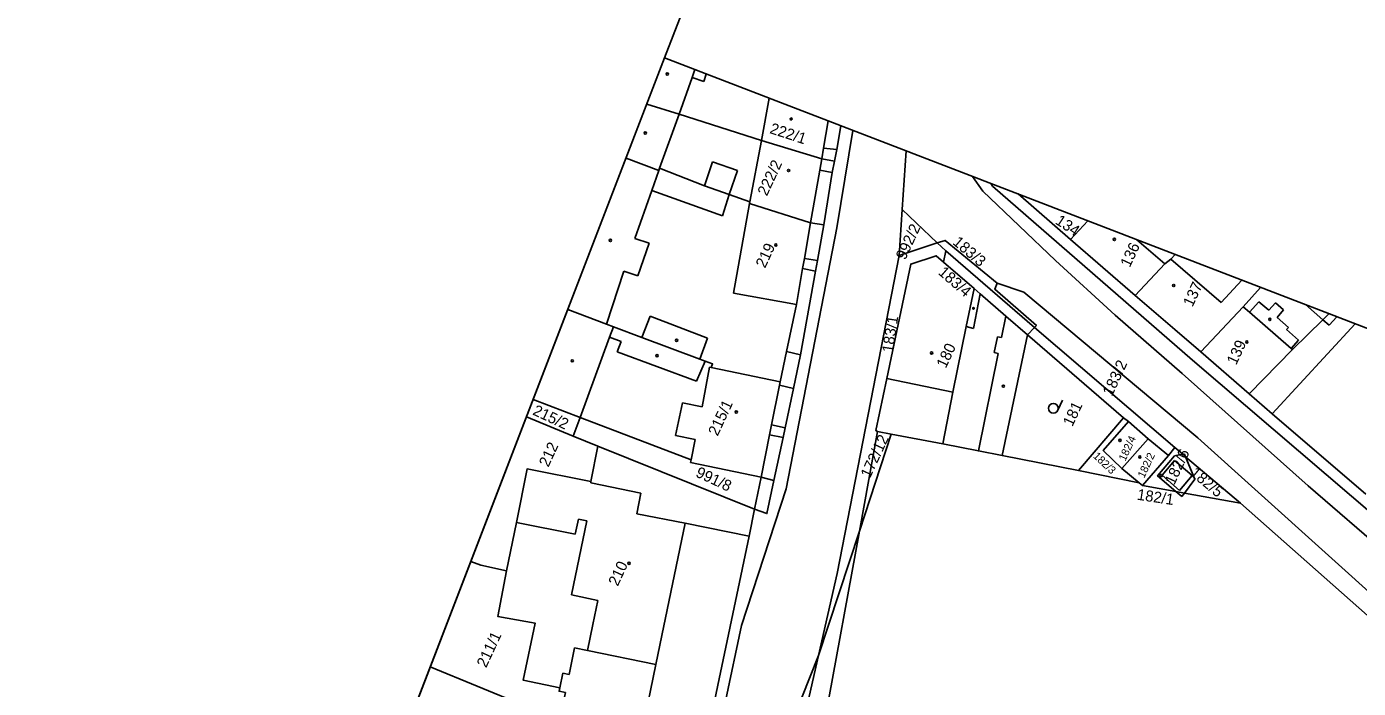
# Model space of a CAD drawing. Extents: x -755344 to -754412, y -1162670 to -1161477.
# Drawn here: x -755140.6 to -754935.5, y -1161770.1 to -1161668.2 of the extents above; entities that cross this region are included whole.
import ezdxf

# ---------------------------------------------------------------- set-up
doc = ezdxf.new("R2010")
doc.units = 0
for name, color, linetype in [('Formát', 7, 'Continuous'), ('Vrstva 55', 7, 'Continuous'), ('Vrstva 56', 7, 'Continuous'), ('Vrstva 57', 7, 'Continuous'), ('Vrstva 58', 7, 'Continuous'), ('Vrstva 59', 7, 'Continuous')]:
    doc.layers.add(name, color=color, linetype=linetype)

msp = doc.modelspace()

# ---------------------------------------------------------------- linework, layer by layer
at = {"layer": 'Formát'}
for q in [(-754966.95, -1161477.04), (-755344.08, -1162456.97), (-755344.08, -1162456.97)]:
    msp.add_line((-755042.37, -1161673.02), q, dxfattribs=at)
msp.add_lwpolyline([(-754488.01, -1161886.37), (-754789.71, -1162670.32), (-755344.08, -1162456.97), (-755042.37, -1161673.02)], close=True, dxfattribs=at)
for points in [[(-755344.08, -1162456.97), (-754789.71, -1162670.32), (-754488.01, -1161886.37), (-755042.37, -1161673.02)], [(-755344.08, -1162456.97), (-754789.71, -1162670.32), (-754488.01, -1161886.37), (-755042.37, -1161673.02)], [(-754789.71, -1162670.32), (-754488.01, -1161886.37), (-755042.37, -1161673.02), (-755344.08, -1162456.97)]]:
    msp.add_lwpolyline(points, dxfattribs=at)
at = {"layer": 'Vrstva 55'}
for p, q in [((-754987.94, -1161693.97), (-754979.83, -1161700.97)), ((-755005.78, -1161696.36), (-755006.24, -1161703.45)), ((-755000.37, -1161701.51), (-755005.78, -1161696.36)), ((-755006.24, -1161703.45), (-755000.37, -1161701.51)), ((-754999.07, -1161702.74), (-755000.37, -1161701.51)), ((-754979.83, -1161700.97), (-754969.9, -1161709.58)), ((-754999.42, -1161704.46), (-754999.07, -1161702.74)), ((-754999.07, -1161702.74), (-754985.41, -1161714.55)), ((-754948.77, -1161727.83), (-754936.01, -1161713.96)), ((-754990.38, -1161734.22), (-754986.49, -1161715.65)), ((-754985.41, -1161714.55), (-754986.49, -1161715.65)), ((-754971.69, -1161728.46), (-754986.49, -1161715.65)), ((-754963.8, -1161733.02), (-754985.41, -1161714.55)), ((-754959.79, -1161718.27), (-754952.34, -1161724.76)), ((-754952.34, -1161724.76), (-754948.77, -1161727.83)), ((-754978.64, -1161736.57), (-754971.69, -1161728.46)), ((-754970.94, -1161729.03), (-754971.69, -1161728.46)), ((-754948.77, -1161727.83), (-754934.36, -1161740.2)), ((-755009.58, -1161730.57), (-755012.38, -1161745.91)), ((-755009.58, -1161730.57), (-755007.48, -1161730.96)), ((-754967.88, -1161731.67), (-754970.94, -1161729.03)), ((-755012.38, -1161745.91), (-755007.48, -1161730.96)), ((-754967.88, -1161731.67), (-754971.93, -1161736.25)), ((-754964.78, -1161734.24), (-754967.88, -1161731.67)), ((-755028.51, -1161742.5), (-755052.64, -1161732.78)), ((-754990.38, -1161734.22), (-754978.64, -1161736.57)), ((-754964.78, -1161734.24), (-754968.79, -1161738.86)), ((-754963.8, -1161733.02), (-754964.78, -1161734.24)), ((-754962.57, -1161734.06), (-754963.8, -1161733.02)), ((-754962.13, -1161734.44), (-754962.57, -1161734.06)), ((-754953.69, -1161741.58), (-754962.13, -1161734.44)), ((-754978.64, -1161736.57), (-754969.27, -1161738.43)), ((-754971.93, -1161736.25), (-754969.27, -1161738.43)), ((-755028.51, -1161742.5), (-755027.52, -1161737.6)), ((-755027.52, -1161737.6), (-755025.54, -1161738.11)), ((-754969.27, -1161738.43), (-754968.79, -1161738.86)), ((-754968.79, -1161738.86), (-754963.61, -1161739.79)), ((-754963.61, -1161739.79), (-754962.32, -1161740.03)), ((-754962.32, -1161740.03), (-754953.69, -1161741.58)), ((-755029.37, -1161746.66), (-755028.51, -1161742.5)), ((-755036.5, -1161780.73), (-755029.37, -1161746.66)), ((-755018.69, -1161780.44), (-755012.38, -1161745.91)), ((-755012.38, -1161745.91), (-755018.66, -1161765.05)), ((-755018.66, -1161765.05), (-755023.99, -1161778.44)), ((-755063.99, -1161772.75), (-755078.47, -1161766.81))]:
    msp.add_line(p, q, dxfattribs=at)
for points in [[(-755045.1, -1161680.12), (-755040.15, -1161681.69), (-755027.46, -1161685.72), (-755018.17, -1161688.54), (-755016.23, -1161688.9)], [(-755013.38, -1161684.18), (-755015.84, -1161699.17), (-755023.66, -1161739.37), (-755030.54, -1161760.43), (-755032.94, -1161771.83), (-755032.59, -1161783.86), (-755042.91, -1161835.1), (-755052.57, -1161882.7), (-755054.53, -1161882.87), (-755056.71, -1161887.12)], [(-755016.23, -1161688.9), (-755015.87, -1161687.12), (-755015.22, -1161683.47)], [(-755005.78, -1161696.36), (-755005.19, -1161687.33)], [(-755017.87, -1161698.7), (-755019.88, -1161698.39), (-755029.28, -1161695.42), (-755029.22, -1161695.16), (-755032.44, -1161694.05), (-755036.25, -1161692.73), (-755043.15, -1161689.97), (-755043.28, -1161690.35), (-755048.31, -1161688.46)], [(-755017.87, -1161698.7), (-755016.58, -1161690.66), (-755016.23, -1161688.9)], [(-754992.13, -1161692.36), (-754991.87, -1161692.75), (-754961.05, -1161719.56), (-754924.16, -1161751.14), (-754883.24, -1161788.9), (-754859.67, -1161809.81)], [(-755022.5, -1161723.9), (-755021.42, -1161718.75), (-755019.14, -1161705.86), (-755018.84, -1161704.19), (-755017.87, -1161698.7)], [(-754979.83, -1161700.97), (-754977.18, -1161698.11)], [(-754985.41, -1161714.55), (-754985.11, -1161714.24), (-754991.52, -1161708.65), (-754991.16, -1161707.68), (-754999.16, -1161701.11), (-755000.37, -1161701.51)], [(-755006.24, -1161703.45), (-755015.79, -1161752.42), (-755018.66, -1161765.05)], [(-754999.42, -1161704.46), (-755000.57, -1161703.47), (-755004.47, -1161704.76), (-755008.12, -1161722.39), (-755009.83, -1161730.4), (-755009.58, -1161730.57)], [(-754969.9, -1161709.58), (-754965.35, -1161704.72), (-754964.42, -1161704), (-754963.75, -1161703.28)], [(-754986.49, -1161715.65), (-754989.82, -1161712.77), (-754993.77, -1161709.36), (-754994.71, -1161708.54), (-754999.42, -1161704.46)], [(-754969.9, -1161709.58), (-754963.77, -1161714.86), (-754959.79, -1161718.27)], [(-754959.79, -1161718.27), (-754953.28, -1161711.36), (-754950.58, -1161708.35)], [(-755022.5, -1161723.9), (-755024.69, -1161723.43), (-755024.58, -1161722.88), (-755035.2, -1161720.68), (-755034.98, -1161720.14), (-755036.15, -1161719.7), (-755036.96, -1161719.39), (-755045.89, -1161716.05), (-755050.24, -1161714.41), (-755051.31, -1161714.01), (-755057.28, -1161711.76)], [(-754952.34, -1161724.76), (-754945.68, -1161717.94), (-754941, -1161713.33), (-754940.05, -1161712.4)], [(-755025.54, -1161738.11), (-755024.12, -1161731.47), (-755023.8, -1161729.98), (-755022.5, -1161723.9)], [(-755062.62, -1161725.64), (-755055.4, -1161728.39), (-755038.3, -1161734.91)], [(-755052.64, -1161732.78), (-755056.45, -1161731.25), (-755063.65, -1161728.31)], [(-754971.93, -1161736.25), (-754974.81, -1161733.49), (-754970.94, -1161729.03)], [(-755007.48, -1161730.96), (-754999.54, -1161732.44), (-754994.03, -1161733.53), (-754990.38, -1161734.22)], [(-755052.64, -1161732.78), (-755053.71, -1161738.24), (-755063.56, -1161736.32), (-755065.16, -1161744.58), (-755066.7, -1161752.01)], [(-754963.61, -1161739.79), (-754966.45, -1161737.38), (-754963.82, -1161734.29), (-754962.57, -1161734.06)], [(-754962.13, -1161734.44), (-754960.7, -1161737.88), (-754962.32, -1161740.03)], [(-755038.3, -1161734.91), (-755038.38, -1161735.3), (-755027.52, -1161737.6)], [(-755025.54, -1161738.11), (-755026.62, -1161743.19), (-755028.51, -1161742.5)], [(-754790.69, -1161920.17), (-754823.33, -1161865.1), (-754831.37, -1161854.01), (-754842.43, -1161841.79), (-754855.01, -1161828.87), (-754953.69, -1161741.58)], [(-755066.7, -1161752.01), (-755068.08, -1161759.03), (-755062.31, -1161760.06), (-755064.15, -1161768.86), (-755058.51, -1161770.01), (-755058.63, -1161770.54), (-755057.66, -1161770.75), (-755058.23, -1161773.52), (-755045.73, -1161776.2), (-755043.71, -1161766.41), (-755042.79, -1161761.96), (-755039.2, -1161744.67), (-755029.37, -1161746.66)], [(-755072.22, -1161750.59), (-755070.67, -1161751.12), (-755066.7, -1161752.01)]]:
    msp.add_lwpolyline(points, dxfattribs=at)
at = {"layer": 'Vrstva 56'}
for p, q in [((-755038.11, -1161676.04), (-755037.71, -1161674.82)), ((-755040.15, -1161681.69), (-755038.11, -1161676.04)), ((-755038.11, -1161676.04), (-755036.35, -1161676.66)), ((-755036.35, -1161676.66), (-755035.95, -1161675.52)), ((-755035.95, -1161675.52), (-755035.73, -1161675.58)), ((-755027.46, -1161685.72), (-755026.28, -1161679.22)), ((-755043.15, -1161689.97), (-755040.15, -1161681.69)), ((-755017.16, -1161682.73), (-755017.89, -1161686.93)), ((-755029.22, -1161695.16), (-755027.46, -1161685.72)), ((-755017.89, -1161686.93), (-755018.17, -1161688.54)), ((-755017.89, -1161686.93), (-755015.87, -1161687.12)), ((-755036.25, -1161692.73), (-755035.01, -1161689.04)), ((-755035.01, -1161689.04), (-755031.17, -1161690.35)), ((-755018.17, -1161688.54), (-755018.47, -1161690.29)), ((-755043.28, -1161690.35), (-755044.33, -1161693.43)), ((-755031.17, -1161690.35), (-755032.44, -1161694.05)), ((-755018.47, -1161690.29), (-755019.88, -1161698.39)), ((-755018.47, -1161690.29), (-755016.58, -1161690.66)), ((-754993.37, -1161693.51), (-754994.94, -1161691.28)), ((-755044.33, -1161693.43), (-755046.94, -1161700.81)), ((-755033.47, -1161697.33), (-755044.33, -1161693.43)), ((-754982.15, -1161704.19), (-754993.37, -1161693.51)), ((-755032.44, -1161694.05), (-755033.47, -1161697.33)), ((-755031.76, -1161709.25), (-755029.28, -1161695.42)), ((-755019.88, -1161698.39), (-755020.83, -1161703.89)), ((-755046.94, -1161700.81), (-755044.77, -1161701.56)), ((-755044.77, -1161701.56), (-755046.5, -1161706.59)), ((-754969.66, -1161701.01), (-754965.35, -1161704.72)), ((-755020.83, -1161703.89), (-755021.11, -1161705.47)), ((-755020.83, -1161703.89), (-755018.84, -1161704.19)), ((-755048.66, -1161705.85), (-755051.31, -1161714.01)), ((-755046.5, -1161706.59), (-755048.66, -1161705.85)), ((-755021.11, -1161705.47), (-755022.06, -1161710.98)), ((-755021.11, -1161705.47), (-755019.14, -1161705.86)), ((-754972.97, -1161712.61), (-754982.15, -1161704.19)), ((-754964.42, -1161704), (-754956.65, -1161710.67)), ((-754991.16, -1161707.68), (-754987.03, -1161709.11)), ((-754953.45, -1161707.25), (-754956.65, -1161710.67)), ((-755022.06, -1161710.98), (-755031.76, -1161709.25)), ((-754994.71, -1161708.54), (-754995.92, -1161714.4)), ((-754994.8, -1161714.66), (-754993.77, -1161709.36)), ((-754987.03, -1161709.11), (-754960.25, -1161731.5)), ((-755022.06, -1161710.98), (-755023.6, -1161718.23)), ((-754953.28, -1161711.36), (-754952.29, -1161712.19)), ((-754952.29, -1161712.19), (-754950.83, -1161710.56)), ((-754950.83, -1161710.56), (-754949.33, -1161711.87)), ((-754949.33, -1161711.87), (-754948.26, -1161710.72)), ((-754948.26, -1161710.72), (-754947.03, -1161711.83)), ((-754947.03, -1161711.83), (-754948.04, -1161712.99)), ((-754943.67, -1161711.01), (-754941, -1161713.33)), ((-755045.89, -1161716.05), (-755044.58, -1161712.76)), ((-755044.58, -1161712.76), (-755035.76, -1161716.18)), ((-754989.82, -1161712.77), (-754990.49, -1161716.08)), ((-754962.66, -1161721.63), (-754972.97, -1161712.61)), ((-754952.29, -1161712.19), (-754945.87, -1161717.78)), ((-754948.04, -1161712.99), (-754946.27, -1161714.52)), ((-754941, -1161713.33), (-754940.01, -1161714.16)), ((-754940.01, -1161714.16), (-754938.83, -1161712.87)), ((-755050.84, -1161716.03), (-755055.4, -1161728.39)), ((-755050.84, -1161716.03), (-755050.24, -1161714.41)), ((-755049.08, -1161716.71), (-755050.84, -1161716.03)), ((-755035.76, -1161716.18), (-755036.96, -1161719.39)), ((-754998, -1161724.47), (-754995.92, -1161714.4)), ((-754995.92, -1161714.4), (-754994.8, -1161714.66)), ((-754991.11, -1161715.96), (-754991.62, -1161718.4)), ((-754990.49, -1161716.08), (-754991.11, -1161715.96)), ((-754946.27, -1161714.52), (-754946.57, -1161714.86)), ((-754946.57, -1161714.86), (-754944.75, -1161716.46)), ((-755049.66, -1161718.28), (-755049.08, -1161716.71)), ((-755024.58, -1161722.88), (-755023.6, -1161718.23)), ((-755021.42, -1161718.75), (-755023.6, -1161718.23)), ((-754944.75, -1161716.46), (-754945.87, -1161717.78)), ((-754945.87, -1161717.78), (-754945.68, -1161717.94)), ((-755037.48, -1161722.82), (-755049.66, -1161718.28)), ((-755036.15, -1161719.7), (-755037.48, -1161722.82)), ((-754990.99, -1161718.52), (-754994.03, -1161733.53)), ((-754991.62, -1161718.4), (-754990.99, -1161718.52)), ((-755036.61, -1161726.74), (-755035.47, -1161720.63)), ((-755035.47, -1161720.63), (-755035.2, -1161720.68)), ((-754962.66, -1161721.63), (-754943.25, -1161738.89)), ((-755025.91, -1161729.53), (-755024.69, -1161723.43)), ((-755008.12, -1161722.39), (-754998, -1161724.47)), ((-755040.69, -1161731.15), (-755039.61, -1161726.11)), ((-755039.61, -1161726.11), (-755036.61, -1161726.74)), ((-754998, -1161724.47), (-754999.54, -1161732.44)), ((-755055.4, -1161728.39), (-755056.45, -1161731.25)), ((-755026.21, -1161731.04), (-755025.91, -1161729.53)), ((-755025.91, -1161729.53), (-755023.8, -1161729.98)), ((-755037.65, -1161731.78), (-755040.69, -1161731.15)), ((-755038.3, -1161734.91), (-755037.65, -1161731.78)), ((-755026.21, -1161731.04), (-755027.52, -1161737.6)), ((-755024.12, -1161731.47), (-755026.21, -1161731.04)), ((-754931.36, -1161757.54), (-754960.25, -1161731.5)), ((-754962.57, -1161734.06), (-754962.3, -1161734.02)), ((-754962.3, -1161734.02), (-754962.13, -1161734.44)), ((-754965.75, -1161737.28), (-754963.83, -1161735.02)), ((-754963.83, -1161735.02), (-754961.12, -1161737.33)), ((-755053.75, -1161738.45), (-755053.71, -1161738.24)), ((-755053.75, -1161738.45), (-755046.02, -1161740.06)), ((-754963.05, -1161739.61), (-754965.75, -1161737.28)), ((-754961.12, -1161737.33), (-754963.05, -1161739.61)), ((-755046.02, -1161740.06), (-755046.67, -1161743.21)), ((-754962.71, -1161740.56), (-754963.61, -1161739.79)), ((-754962.32, -1161740.03), (-754962.71, -1161740.56)), ((-754943.25, -1161738.89), (-754926.26, -1161753.63)), ((-755065.16, -1161744.58), (-755056.13, -1161746.34)), ((-755056.71, -1161755.68), (-755054.35, -1161744.29)), ((-755056.13, -1161746.34), (-755055.66, -1161744.06)), ((-755055.66, -1161744.06), (-755054.87, -1161744.19)), ((-755054.35, -1161744.29), (-755054.87, -1161744.19)), ((-755046.67, -1161743.21), (-755039.2, -1161744.67)), ((-755052.67, -1161756.55), (-755056.71, -1161755.68)), ((-755053.42, -1161760.28), (-755052.67, -1161756.55)), ((-755054.23, -1161764.27), (-755053.42, -1161760.28)), ((-755056.23, -1161763.86), (-755057.08, -1161767.98)), ((-755054.23, -1161764.27), (-755056.23, -1161763.86)), ((-755043.71, -1161766.41), (-755054.23, -1161764.27)), ((-755018.66, -1161765.05), (-755021.88, -1161779.23)), ((-755058.05, -1161767.78), (-755058.51, -1161770.01)), ((-755057.08, -1161767.98), (-755058.05, -1161767.78))]:
    msp.add_line(p, q, dxfattribs=at)
at = {"layer": 'Vrstva 58'}
msp.add_line((-754981.82, -1161727.28), (-754981.08, -1161725.7), dxfattribs=at)
msp.add_circle((-754982.5, -1161726.97), 0.75, dxfattribs=at)
at = {"layer": 'Vrstva 59'}
msp.add_line((-755022.71, -1161682.34), (-755022.95, -1161682.24), dxfattribs=at)
for centre, radius in [((-755041.96, -1161675.51), 0.175), ((-755045.36, -1161684.58), 0.175), ((-755023.27, -1161690.35), 0.175), ((-755050.72, -1161701.12), 0.175), ((-755025.24, -1161701.81), 0.175), ((-754973.1, -1161700.96), 0.175), ((-754963.96, -1161708.06), 0.175), ((-754994.8, -1161711.58), 0.117), ((-754949.15, -1161713.28), 0.175), ((-755040.52, -1161716.51), 0.175), ((-755001.25, -1161718.44), 0.175), ((-754952.7, -1161716.76), 0.175), ((-755056.6, -1161719.66), 0.175), ((-755043.53, -1161718.87), 0.175), ((-754990.18, -1161723.56), 0.175), ((-755031.34, -1161727.56), 0.175), ((-754972.24, -1161731.92), 0.175), ((-754969.18, -1161734.46), 0.175), ((-754965.91, -1161737.34), 0.175), ((-755047.84, -1161750.84), 0.175)]:
    msp.add_circle(centre, radius, dxfattribs=at)
msp.add_arc((-755022.87, -1161682.4), 0.175, 118.333, 19.5683, dxfattribs=at)

# ---------------------------------------------------------------- texts
at = {"layer": 'Vrstva 57'}
for s, height, rotation, p in [('222/1', 1.7, 342.0551, (-755026.29, -1161684.58)), ('222/2', 1.7, 65, (-755026.62, -1161694.39)), ('134', 1.7, 326.5771, (-754982.33, -1161698.46)), ('992/2', 1.7, 65, (-755005.31, -1161704.24)), ('219', 1.7, 65, (-755026.9, -1161705.49)), ('183/3', 1.7, 319.5822, (-754998.12, -1161701.6)), ('136', 1.7, 65, (-754970.73, -1161705.39)), ('183/4', 1.7, 318.8839, (-755000.35, -1161706.22)), ('137', 1.7, 65, (-754961.07, -1161711.47)), ('183/1', 1.7, 81.3851, (-755007.23, -1161718.48)), ('180', 1.7, 65, (-754999.06, -1161720.91)), ('139', 1.7, 65, (-754954.34, -1161720.41)), ('183/2', 1.7, 65, (-754973.46, -1161725.21)), ('215/1', 1.7, 65, (-755034.21, -1161731.35)), ('181', 1.7, 65, (-754979.57, -1161729.89)), ('215/2', 1.7, 335, (-755062.82, -1161727.89)), ('212', 1.7, 65, (-755060.28, -1161736.13)), ('172/12', 1.7, 65, (-755010.74, -1161737.84)), ('182/4', 1.2, 65, (-754971.42, -1161735.2)), ('182/3', 1.2, 316.5042, (-754976.47, -1161734.44)), ('182/2', 1.2, 65, (-754968.5, -1161737.8)), ('182/6', 1.7, 65, (-754963.88, -1161738.9)), ('991/8', 1.7, 335, (-755037.72, -1161737.43)), ('182/5', 1.7, 320.0035, (-754961.57, -1161737.14)), ('182/1', 1.7, 351.505, (-754969.68, -1161741.04)), ('210', 1.7, 65, (-755049.59, -1161754.47)), ('211/1', 1.7, 65, (-755069.86, -1161767.03))]:
    msp.add_text(s, height=height, rotation=rotation, dxfattribs=at).set_placement(p)

doc.saveas('drawing.dxf')
